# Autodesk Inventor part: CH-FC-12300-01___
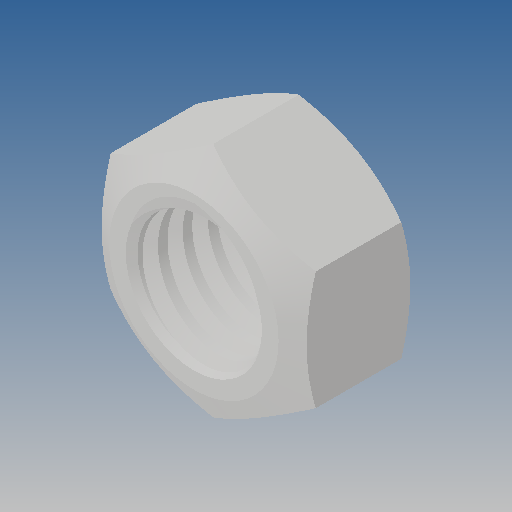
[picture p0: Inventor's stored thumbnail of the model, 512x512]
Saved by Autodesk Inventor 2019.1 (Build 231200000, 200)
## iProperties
Created: 2010-06
Part Number: CH-FC-12300-01___
Material: Ogólny
Document SubType Name: Modeling
Designer: CADENGINEERING4
Density: 1 g/cm^3
Appearance: Domyślna
Author: CADENGINEERING4
Revision Number: ANY
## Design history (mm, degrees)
feature "NONE"
node "Bryła1"
